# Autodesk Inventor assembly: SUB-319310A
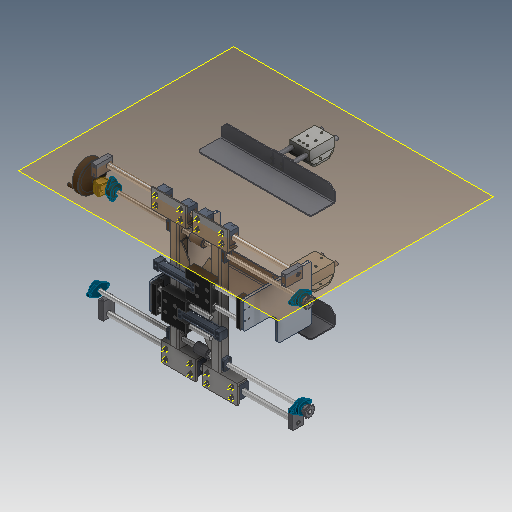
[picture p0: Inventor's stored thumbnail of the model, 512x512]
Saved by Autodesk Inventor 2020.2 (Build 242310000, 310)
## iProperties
Created: 2000-01
Part Number: SUB-319310A
Document SubType Name: Assembly
Designer: cmcgourin
Mass: 58892.8 g
Surface Area: 31424.7 cm^2
Volume: 13610.9 cm^3
Density: 4.32689 g/cm^3
Control State: 0
Master: False
Checked Out: False
Shininess: 0.0
Length Units: 11269
Angle Units: 11279
Time Units: 11290
Mass Units: 11283
Length Display Precision: 3
Angle Display Precision: 2
Compacted: True
Dimensions: 801,9x772,9x1220,3 mm
Mass: 58,893 kg
DocNumber: SUB-319310.iam
Folder: .
VDS_Category: 3D Komponenten
Density: 0.0
Volumn: 0.0
Area: 0.0
PropertySet Name: Model Information
Author: cmcgourin
Revision Number: -
Title: SUB-319310A
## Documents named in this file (33)
- D:\07 - DEMODATEN\OTX 2019 - Dataset - UPDATE - Dez2019\Designs\07-Packing machine\SUB-319310.iam
- D:\07 - DEMODATEN\OTX 2019 - Dataset - UPDATE - Dez2019\Designs\07-Packing machine\A105229.iam
- D:\07 - DEMODATEN\OTX 2019 - Dataset - UPDATE - Dez2019\Designs\07-Packing machine\Parts\ADSK-011474.ipt
- D:\07 - DEMODATEN\OTX 2019 - Dataset - UPDATE - Dez2019\Designs\07-Packing machine\Parts\ADSK-011327.ipt
- D:\07 - DEMODATEN\OTX 2019 - Dataset - UPDATE - Dez2019\Designs\07-Packing machine\500571.iam
- D:\07 - DEMODATEN\OTX 2019 - Dataset - UPDATE - Dez2019\Designs\07-Packing machine\Parts\ADSK-011325.ipt
- D:\07 - DEMODATEN\OTX 2019 - Dataset - UPDATE - Dez2019\Designs\07-Packing machine\Parts\ADSK-011507.ipt
- D:\07 - DEMODATEN\OTX 2019 - Dataset - UPDATE - Dez2019\Designs\07-Packing machine\Parts\ADSK-011515.ipt
- D:\07 - DEMODATEN\OTX 2019 - Dataset - UPDATE - Dez2019\Designs\07-Packing machine\Parts\ADSK-011726.ipt
- D:\07 - DEMODATEN\OTX 2019 - Dataset - UPDATE - Dez2019\Designs\07-Packing machine\Parts\ADSK-011516.ipt
- D:\07 - DEMODATEN\OTX 2019 - Dataset - UPDATE - Dez2019\Designs\07-Packing machine\Parts\ADSK-011714.ipt
- D:\07 - DEMODATEN\OTX 2019 - Dataset - UPDATE - Dez2019\Designs\07-Packing machine\Parts\ADSK-011333.ipt
- D:\07 - DEMODATEN\OTX 2019 - Dataset - UPDATE - Dez2019\Designs\07-Packing machine\Parts\ADSK-011517.ipt
- D:\07 - DEMODATEN\OTX 2019 - Dataset - UPDATE - Dez2019\Designs\07-Packing machine\Parts\ADSK-011768.ipt
- D:\07 - DEMODATEN\OTX 2019 - Dataset - UPDATE - Dez2019\Designs\07-Packing machine\Parts\ADSK-011309.ipt
- D:\07 - DEMODATEN\OTX 2019 - Dataset - UPDATE - Dez2019\Designs\07-Packing machine\Parts\ADSK-011723.ipt
- D:\07 - DEMODATEN\OTX 2019 - Dataset - UPDATE - Dez2019\Designs\07-Packing machine\Parts\ADSK-011565.ipt
- D:\07 - DEMODATEN\OTX 2019 - Dataset - UPDATE - Dez2019\Designs\07-Packing machine\Parts\ADSK-011627.ipt
- D:\07 - DEMODATEN\OTX 2019 - Dataset - UPDATE - Dez2019\Designs\07-Packing machine\Parts\ADSK-011639.ipt
- D:\07 - DEMODATEN\OTX 2019 - Dataset - UPDATE - Dez2019\Designs\07-Packing machine\A102253.iam
- D:\07 - DEMODATEN\OTX 2019 - Dataset - UPDATE - Dez2019\Content Center Files\de-DE\ISO 4762(2)\ISO 4762 - M8 x 16ISO.ipt
- D:\07 - DEMODATEN\OTX 2019 - Dataset - UPDATE - Dez2019\Content Center Files\de-DE\ISO 4762(2)\ISO 4762 - M8 x 60ISO.ipt
- D:\07 - DEMODATEN\OTX 2019 - Dataset - UPDATE - Dez2019\Content Center Files\de-DE\ISO 4762(2)\ISO 4762 - M8 x 45ISO.ipt
- D:\07 - DEMODATEN\OTX 2019 - Dataset - UPDATE - Dez2019\Content Center Files\de-DE\ISO 4762(2)\ISO 4762 - M6 x 30ISO.ipt
- D:\07 - DEMODATEN\OTX 2019 - Dataset - UPDATE - Dez2019\Content Center Files\de-DE\ISO 4762(2)\ISO 4762 - M12 x 25ISO.ipt
- D:\07 - DEMODATEN\OTX 2019 - Dataset - UPDATE - Dez2019\Content Center Files\de-DE\DIN 125-1  B\DIN 125-1 - B 8,4.ipt
- D:\07 - DEMODATEN\OTX 2019 - Dataset - UPDATE - Dez2019\Content Center Files\de-DE\ISO 4032(1)\ISO 4032 - M8DIN EN.ipt
- D:\07 - DEMODATEN\OTX 2019 - Dataset - UPDATE - Dez2019\Content Center Files\de-DE\ISO 2491 - A\ISO 2491 - A  5 x 3 x 22.ipt
- D:\07 - DEMODATEN\OTX 2019 - Dataset - UPDATE - Dez2019\Content Center Files\de-DE\ISO 4028\ISO 4028 - M5 x 10 - ISO.ipt
- D:\07 - DEMODATEN\OTX 2019 - Dataset - UPDATE - Dez2019\Content Center Files\de-DE\ISO 2491 - A\ISO 2491 - A  5 x 3 x 56.ipt
- D:\07 - DEMODATEN\OTX 2019 - Dataset - UPDATE - Dez2019\Content Center Files\de-DE\DIN 125-1  B\DIN 125-1 - B 6,4.ipt
- D:\07 - DEMODATEN\OTX 2019 - Dataset - UPDATE - Dez2019\Content Center Files\de-DE\ISO 4762(2)\ISO 4762 - M6 x 20ISO.ipt
- D:\07 - DEMODATEN\OTX 2019 - Dataset - UPDATE - Dez2019\Content Center Files\de-DE\ISO 4762(2)\ISO 4762 - M6 x 50ISO.ipt
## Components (150 placed, 32 different names)
1. 500571:1 [sub-assembly] — Fluchtend:16, Fluchtend:18, Passend:79, Passend:86, Passend:87, Passend:88, Passend:89, Passend:90, Passend:91, Passend:108, Passend:111, Passend:122, Passend:123, Passend:133, Passend:136, Passend:137, Passend:183, Passend:184, Passend:185, Passend:186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
2. 500571:2 [sub-assembly] — Fluchtend:17, Passend:78, Fluchtend:19, Passend:80, Passend:81, Passend:82, Passend:83, Passend:84, Passend:85, Passend:112, Passend:113, Passend:120, Passend:121, Passend:132, Passend:134, Passend:135, Passend:176, Passend:179, Passend:180, Passend:181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
3. ADSK-011474:1 — Fluchtend:238, Mate:71, Passend:267, Passend:269, Passend:271, Passend:273, Fluchtend:239, Fluchtend:244, Fluchtend:246
4. ADSK-011327:1 — Einfügen:71, Passend:263, Einfügen:82
5. ADSK-011327:2 — Einfügen:49, Fluchtend:23
6. ADSK-011327:3 — Einfügen:50, Fluchtend:23, Winkel:13
7. ADSK-011507:2 — Passend:244, Passend:262, Einfügen:71, Einfügen:72
8. ADSK-011325:6 — Passend:108, Passend:187, Passend:188, Passend:244
9. ADSK-011714:3 — Passend:175, Fluchtend:24, Passend:178, Einfügen:69
10. ADSK-011515:1 — Passend:300, Fluchtend:309, Passend:302, Passend:304, Passend:307, Fluchtend:308
11. ADSK-011516:1 — Fluchtend:26, Passend:228, Passend:237, Passend:238, Fluchtend:307, Passend:301, Fluchtend:309, Passend:302, Passend:303, Passend:308, Passend:309, Passend:310
12. ADSK-011726:1 — Passend:303, Passend:304, Passend:307
13. ADSK-011333:1 — Passend:80, Passend:84, Passend:85, Passend:101, Passend:103, Passend:105, Passend:107
14. ADSK-011714:4 — Passend:177, Winkel:14, Fluchtend:24, Fluchtend:25, Passend:255, Fluchtend:308
15. ADSK-011516:2 — Passend:245, Fluchtend:235, Passend:246, Passend:247, Passend:249, Passend:254, Passend:261
16. ADSK-011726:2 — Passend:252, Passend:253, Passend:257
17. ADSK-011517:1 — Mate:44, Mate:48, Mate:50, Flush:7, Passend:254, Passend:257, Passend:258, Passend:259, Passend:260, Passend:261, Passend:311
18. ADSK-011714:5 — Passend:242, Winkel:15, Passend:243, Einfügen:70, Passend:256
19. ADSK-011714:6 — Mate:44, Mate:62, Flush:7, Passend:255, Passend:256
20. ADSK-011333:2 — Passend:81, Passend:82, Passend:83
21. ADSK-011768:1 — Mate:48, Mate:49, Mate:62
22. ADSK-011309:1 — Mate:49, Mate:50, Passend:311
23. ADSK-011723:1 — Einfügen:69, Fluchtend:26, Passend:228, Passend:232, Drehung:1
24. ADSK-011723:2 — Einfügen:70, Passend:245, Fluchtend:235, Passend:246, Passend:248, Passend:250, Drehung:1
25. ADSK-011565:1 — Passend:170, Fluchtend:20, Passend:171
26. ADSK-011627:1 — Mate:70, Flush:9, Flush:10, Passend:264, Passend:265, Fluchtend:237
27. ADSK-011639:1 — Passend:174, Fluchtend:22, Einfügen:49, Einfügen:50
28. A102253:1 [sub-assembly] — Fluchtend:238, Mate:70, Flush:9, Flush:10, Mate:71, Fluchtend:239, Fluchtend:245
29. A105229:1 [sub-assembly] — Passend:133, Passend:136, Passend:137, Passend:170, Fluchtend:20, Passend:171
30. A105229:2 [sub-assembly] — Passend:132, Passend:134, Passend:135, Passend:172, Fluchtend:21, Passend:173
31. ADSK-011333:3 — Passend:86, Passend:90, Passend:91
32. ADSK-011333:4 — Passend:87, Passend:88, Passend:89, Passend:93, Passend:95, Passend:97, Passend:99
33. ADSK-011325:7 — Passend:111, Passend:189, Passend:190
34. ADSK-011325:8 — Passend:112, Passend:191, Passend:192
35. ADSK-011325:9 — Passend:113, Passend:193, Passend:194
36. ADSK-011325:10 — Passend:120, Passend:179, Passend:180
37. ADSK-011325:11 — Passend:121, Passend:181, Passend:182
38. ADSK-011325:12 — Passend:122, Passend:174, Passend:183, Passend:184
39. ADSK-011325:13 — Passend:123, Passend:185, Passend:186
40. ADSK-011565:4 — Passend:172, Fluchtend:21, Passend:173
41. ADSK-011327:4 — Einfügen:72, Passend:263, Winkel:16, Einfügen:81
42. ADSK-011474:2 — Fluchtend:244, Fluchtend:246
43. ADSK-011627:2
44. A102253:2 [sub-assembly] — Fluchtend:245
45. ISO 4762 M12 x 25:3 — Einfügen:81
46. ISO 4762 M12 x 25:4 — Einfügen:82
47. DIN 125-1 B B 6,4:5
48. DIN 125-1 B B 6,4:6
49. DIN 125-1 B B 6,4:7
50. DIN 125-1 B B 6,4:8
51. ISO 4762 M6 x 20:5
52. ISO 4762 M6 x 20:6
53. ISO 4762 M6 x 20:7
54. ISO 4762 M6 x 20:8
55. ISO 4762 M6 x 50:5
56. ISO 4762 M6 x 50:6
57. ISO 4762 M6 x 50:7
58. ISO 4762 M6 x 50:8
59. DIN 125-1 B B 6,4:1 — Passend:267, Passend:275, Passend:277, Passend:279, Passend:281
60. DIN 125-1 B B 6,4:2 — Passend:269
61. DIN 125-1 B B 6,4:3 — Passend:271
62. DIN 125-1 B B 6,4:4 — Passend:273
63. ISO 4762 M6 x 20:1 — Passend:275
64. ISO 4762 M6 x 20:2 — Passend:277
65. ISO 4762 M6 x 20:3 — Passend:279
66. ISO 4762 M6 x 20:4 — Passend:281
67. ISO 4762 M6 x 50:1
68. ISO 4762 M6 x 50:2
69. ISO 4762 M6 x 50:3
70. ISO 4762 M6 x 50:4
71. ISO 2491 A A  5 x 3 x 22:2 — Passend:247, Passend:248, Passend:249, Passend:251
72. ISO 4028 M5 x 10:2 — Passend:250, Passend:251
73. ISO 2491 A A  5 x 3 x 56:2 — Passend:258, Passend:259, Passend:260
74. ISO 2491 A A  5 x 3 x 22:1 — Passend:233, Passend:308, Passend:309, Passend:310
75. ISO 4028 M5 x 10:1 — Passend:232, Passend:233
76. ISO 2491 A A  5 x 3 x 56:1 — Passend:237, Passend:238, Fluchtend:307
77. ISO 4762 M6 x 30:1
78. ISO 4762 M6 x 30:2
79. ISO 4762 M6 x 30:3
80. ISO 4762 M6 x 30:4
81. ISO 4762 M6 x 30:5
82. ISO 4762 M6 x 30:6
83. ISO 4762 M6 x 30:7
84. ISO 4762 M6 x 30:8
85. ISO 4762 M12 x 25:1
86. ISO 4762 M12 x 25:2
87. DIN 125-1 B B 8,4:1 — Passend:196
88. DIN 125-1 B B 8,4:2 — Passend:198
89. DIN 125-1 B B 8,4:3 — Passend:200
90. DIN 125-1 B B 8,4:4 — Passend:202
91. DIN 125-1 B B 8,4:5 — Passend:204
92. DIN 125-1 B B 8,4:6 — Passend:206
93. DIN 125-1 B B 8,4:7 — Passend:208
94. DIN 125-1 B B 8,4:8 — Passend:210
95. DIN 125-1 B B 8,4:9 — Passend:212
96. DIN 125-1 B B 8,4:10 — Passend:214
97. DIN 125-1 B B 8,4:11 — Passend:216
98. DIN 125-1 B B 8,4:12 — Passend:218
99. DIN 125-1 B B 8,4:13 — Passend:220
100. DIN 125-1 B B 8,4:14 — Passend:222
101. DIN 125-1 B B 8,4:15 — Passend:224
102. DIN 125-1 B B 8,4:16 — Passend:226
103. DIN EN 24032 M8:1
104. DIN EN 24032 M8:2
105. DIN EN 24032 M8:3
106. DIN EN 24032 M8:4
107. DIN EN 24032 M8:5
108. DIN EN 24032 M8:6
109. DIN EN 24032 M8:7
110. DIN EN 24032 M8:8
111. DIN EN 24032 M8:9
112. DIN EN 24032 M8:10
113. DIN EN 24032 M8:11
114. DIN EN 24032 M8:12
115. DIN EN 24032 M8:13
116. DIN EN 24032 M8:14
117. DIN EN 24032 M8:15
118. DIN EN 24032 M8:16
119. ISO 4762 M8 x 45:1
120. ISO 4762 M8 x 45:2
121. ISO 4762 M8 x 45:3
122. ISO 4762 M8 x 45:4
123. ISO 4762 M8 x 45:5
124. ISO 4762 M8 x 45:6
125. ISO 4762 M8 x 45:7
126. ISO 4762 M8 x 45:8
127. ISO 4762 M8 x 60:1
128. ISO 4762 M8 x 60:2
129. ISO 4762 M8 x 60:3
130. ISO 4762 M8 x 60:4
131. ISO 4762 M8 x 60:5
132. ISO 4762 M8 x 60:6
133. ISO 4762 M8 x 60:7
134. ISO 4762 M8 x 60:8
135. ISO 4762 M8 x 60:9
136. ISO 4762 M8 x 60:10
137. ISO 4762 M8 x 60:11
138. ISO 4762 M8 x 60:12
139. ISO 4762 M8 x 60:13
140. ISO 4762 M8 x 60:14
141. ISO 4762 M8 x 60:15
142. ISO 4762 M8 x 60:16
143. ISO 4762 M8 x 16:1 — Passend:93
144. ISO 4762 M8 x 16:2 — Passend:95
145. ISO 4762 M8 x 16:3 — Passend:97
146. ISO 4762 M8 x 16:4 — Passend:99
147. ISO 4762 M8 x 16:5 — Passend:101
148. ISO 4762 M8 x 16:6 — Passend:103
149. ISO 4762 M8 x 16:7 — Passend:105
150. ISO 4762 M8 x 16:8 — Passend:107
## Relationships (169: Mate 132, Flush 24, Insert 8, Angle 4, RelateRotation 1)
- Mate:44: ADSK-011517:1 ↔ ADSK-011714:6
- Mate:48: ADSK-011517:1 ↔ ADSK-011768:1
- Mate:49: ADSK-011768:1 ↔ ADSK-011309:1
- Mate:50: ADSK-011517:1 ↔ ADSK-011309:1
- Mate:62: ADSK-011714:6 ↔ ADSK-011768:1
- Flush:7: ADSK-011517:1 ↔ ADSK-011714:6
- Fluchtend:238 [Flush]: ADSK-011474:1 ↔ A102253:1
- Mate:70: ADSK-011627:1 ↔ A102253:1
- Flush:9: ADSK-011627:1 ↔ A102253:1
- Flush:10: ADSK-011627:1 ↔ A102253:1
- Mate:71: ADSK-011474:1 ↔ A102253:1
- Fluchtend:16 [Flush]: 500571:1
- Fluchtend:17 [Flush]: 500571:2
- Fluchtend:18 [Flush]: 500571:1
- Passend:78 [Mate]: 500571:2
- Passend:79 [Mate]: 500571:1
- Fluchtend:19 [Flush]: 500571:2
- Passend:80 [Mate]: 500571:2 ↔ ADSK-011333:1
- Passend:81 [Mate]: 500571:2 ↔ ADSK-011333:2
- Passend:82 [Mate]: 500571:2 ↔ ADSK-011333:2
- Passend:83 [Mate]: 500571:2 ↔ ADSK-011333:2
- Passend:84 [Mate]: 500571:2 ↔ ADSK-011333:1
- Passend:85 [Mate]: 500571:2 ↔ ADSK-011333:1
- Passend:86 [Mate]: 500571:1 ↔ ADSK-011333:3
- Passend:87 [Mate]: 500571:1 ↔ ADSK-011333:4
- Passend:88 [Mate]: 500571:1 ↔ ADSK-011333:4
- Passend:89 [Mate]: 500571:1 ↔ ADSK-011333:4
- Passend:90 [Mate]: 500571:1 ↔ ADSK-011333:3
- Passend:91 [Mate]: 500571:1 ↔ ADSK-011333:3
- Passend:93 [Mate]: ADSK-011333:4 ↔ ISO 4762 M8 x 16:1
- Passend:95 [Mate]: ADSK-011333:4 ↔ ISO 4762 M8 x 16:2
- Passend:97 [Mate]: ADSK-011333:4 ↔ ISO 4762 M8 x 16:3
- Passend:99 [Mate]: ADSK-011333:4 ↔ ISO 4762 M8 x 16:4
- Passend:101 [Mate]: ADSK-011333:1 ↔ ISO 4762 M8 x 16:5
- Passend:103 [Mate]: ADSK-011333:1 ↔ ISO 4762 M8 x 16:6
- Passend:105 [Mate]: ADSK-011333:1 ↔ ISO 4762 M8 x 16:7
- Passend:107 [Mate]: ADSK-011333:1 ↔ ISO 4762 M8 x 16:8
- Passend:108 [Mate]: 500571:1 ↔ ADSK-011325:6
- Passend:111 [Mate]: 500571:1 ↔ ADSK-011325:7
- Passend:112 [Mate]: 500571:2 ↔ ADSK-011325:8
- Passend:113 [Mate]: 500571:2 ↔ ADSK-011325:9
- Passend:120 [Mate]: 500571:2 ↔ ADSK-011325:10
- Passend:121 [Mate]: 500571:2 ↔ ADSK-011325:11
- Passend:122 [Mate]: 500571:1 ↔ ADSK-011325:12
- Passend:123 [Mate]: 500571:1 ↔ ADSK-011325:13
- Passend:132 [Mate]: 500571:2 ↔ A105229:2
- Passend:133 [Mate]: 500571:1 ↔ A105229:1
- Passend:134 [Mate]: 500571:2 ↔ A105229:2
- Passend:135 [Mate]: 500571:2 ↔ A105229:2
- Passend:136 [Mate]: 500571:1 ↔ A105229:1
- Passend:137 [Mate]: 500571:1 ↔ A105229:1
- Passend:170 [Mate]: ADSK-011565:1 ↔ A105229:1
- Fluchtend:20 [Flush]: ADSK-011565:1 ↔ A105229:1
- Passend:171 [Mate]: ADSK-011565:1 ↔ A105229:1
- Passend:172 [Mate]: A105229:2 ↔ ADSK-011565:4
- Fluchtend:21 [Flush]: A105229:2 ↔ ADSK-011565:4
- Passend:173 [Mate]: A105229:2 ↔ ADSK-011565:4
- Passend:174 [Mate]: ADSK-011639:1 ↔ ADSK-011325:12
- Fluchtend:22 [Flush]: ADSK-011639:1
- Einfügen:49 [Insert]: ADSK-011327:2 ↔ ADSK-011639:1
- Einfügen:50 [Insert]: ADSK-011327:3 ↔ ADSK-011639:1
- Fluchtend:23 [Flush]: ADSK-011327:2 ↔ ADSK-011327:3
- Winkel:13 [Angle]: ADSK-011327:3
- Passend:175 [Mate]: ADSK-011714:3
- Passend:176 [Mate]: 500571:2
- Passend:177 [Mate]: ADSK-011714:4
- Winkel:14 [Angle]: ADSK-011714:4
- Fluchtend:24 [Flush]: ADSK-011714:3 ↔ ADSK-011714:4
- Passend:178 [Mate]: ADSK-011714:3
- Fluchtend:25 [Flush]: ADSK-011714:4
- Passend:179 [Mate]: 500571:2 ↔ ADSK-011325:10
- Passend:180 [Mate]: 500571:2 ↔ ADSK-011325:10
- Passend:181 [Mate]: 500571:2 ↔ ADSK-011325:11
- Passend:182 [Mate]: 500571:2 ↔ ADSK-011325:11
- Passend:183 [Mate]: 500571:1 ↔ ADSK-011325:12
- Passend:184 [Mate]: 500571:1 ↔ ADSK-011325:12
- Passend:185 [Mate]: 500571:1 ↔ ADSK-011325:13
- Passend:186 [Mate]: 500571:1 ↔ ADSK-011325:13
- Passend:187 [Mate]: 500571:1 ↔ ADSK-011325:6
- Passend:188 [Mate]: 500571:1 ↔ ADSK-011325:6
- Passend:189 [Mate]: 500571:1 ↔ ADSK-011325:7
- Passend:190 [Mate]: 500571:1 ↔ ADSK-011325:7
- Passend:191 [Mate]: 500571:2 ↔ ADSK-011325:8
- Passend:192 [Mate]: 500571:2 ↔ ADSK-011325:8
- Passend:193 [Mate]: 500571:2 ↔ ADSK-011325:9
- Passend:194 [Mate]: 500571:2 ↔ ADSK-011325:9
- Passend:196 [Mate]: 500571:1 ↔ DIN 125-1 B B 8,4:1
- Passend:198 [Mate]: 500571:1 ↔ DIN 125-1 B B 8,4:2
- Passend:200 [Mate]: 500571:1 ↔ DIN 125-1 B B 8,4:3
- Passend:202 [Mate]: 500571:1 ↔ DIN 125-1 B B 8,4:4
- Passend:204 [Mate]: 500571:2 ↔ DIN 125-1 B B 8,4:5
- Passend:206 [Mate]: 500571:2 ↔ DIN 125-1 B B 8,4:6
- Passend:208 [Mate]: 500571:2 ↔ DIN 125-1 B B 8,4:7
- Passend:210 [Mate]: 500571:2 ↔ DIN 125-1 B B 8,4:8
- Passend:212 [Mate]: 500571:1 ↔ DIN 125-1 B B 8,4:9
- Passend:214 [Mate]: 500571:1 ↔ DIN 125-1 B B 8,4:10
- Passend:216 [Mate]: 500571:1 ↔ DIN 125-1 B B 8,4:11
- Passend:218 [Mate]: 500571:1 ↔ DIN 125-1 B B 8,4:12
- Passend:220 [Mate]: 500571:2 ↔ DIN 125-1 B B 8,4:13
- Passend:222 [Mate]: 500571:2 ↔ DIN 125-1 B B 8,4:14
- Passend:224 [Mate]: 500571:2 ↔ DIN 125-1 B B 8,4:15
- Passend:226 [Mate]: 500571:2 ↔ DIN 125-1 B B 8,4:16
- Einfügen:69 [Insert]: ADSK-011714:3 ↔ ADSK-011723:1
- Fluchtend:26 [Flush]: ADSK-011516:1 ↔ ADSK-011723:1
- Passend:228 [Mate]: ADSK-011516:1 ↔ ADSK-011723:1
- Passend:232 [Mate]: ADSK-011723:1 ↔ ISO 4028 M5 x 10:1
- Passend:233 [Mate]: ISO 2491 A A  5 x 3 x 22:1 ↔ ISO 4028 M5 x 10:1
- Passend:237 [Mate]: ADSK-011516:1 ↔ ISO 2491 A A  5 x 3 x 56:1
- Passend:238 [Mate]: ADSK-011516:1 ↔ ISO 2491 A A  5 x 3 x 56:1
- Fluchtend:307 [Flush]: ADSK-011516:1 ↔ ISO 2491 A A  5 x 3 x 56:1
- Passend:241 [Mate]: 500571:1
- Passend:242 [Mate]: ADSK-011714:5
- Winkel:15 [Angle]: ADSK-011714:5
- Passend:243 [Mate]: ADSK-011714:5
- Einfügen:70 [Insert]: ADSK-011714:5 ↔ ADSK-011723:2
- Passend:244 [Mate]: ADSK-011507:2 ↔ ADSK-011325:6
- Passend:245 [Mate]: ADSK-011516:2 ↔ ADSK-011723:2
- Fluchtend:235 [Flush]: ADSK-011516:2 ↔ ADSK-011723:2
- Passend:246 [Mate]: ADSK-011516:2 ↔ ADSK-011723:2
- Passend:247 [Mate]: ADSK-011516:2 ↔ ISO 2491 A A  5 x 3 x 22:2
- Passend:248 [Mate]: ADSK-011723:2 ↔ ISO 2491 A A  5 x 3 x 22:2
- Passend:249 [Mate]: ADSK-011516:2 ↔ ISO 2491 A A  5 x 3 x 22:2
- Passend:250 [Mate]: ADSK-011723:2 ↔ ISO 4028 M5 x 10:2
- Passend:251 [Mate]: ISO 2491 A A  5 x 3 x 22:2 ↔ ISO 4028 M5 x 10:2
- Passend:252 [Mate]: ADSK-011726:2
- Passend:253 [Mate]: ADSK-011726:2
- Passend:254 [Mate]: ADSK-011516:2 ↔ ADSK-011517:1
- Passend:255 [Mate]: ADSK-011714:4 ↔ ADSK-011714:6
- Passend:256 [Mate]: ADSK-011714:5 ↔ ADSK-011714:6
- Passend:257 [Mate]: ADSK-011726:2 ↔ ADSK-011517:1
- Passend:258 [Mate]: ADSK-011517:1 ↔ ISO 2491 A A  5 x 3 x 56:2
- Passend:259 [Mate]: ADSK-011517:1 ↔ ISO 2491 A A  5 x 3 x 56:2
- Passend:260 [Mate]: ADSK-011517:1 ↔ ISO 2491 A A  5 x 3 x 56:2
- Passend:261 [Mate]: ADSK-011516:2 ↔ ADSK-011517:1
- Passend:262 [Mate]: ADSK-011507:2
- Einfügen:71 [Insert]: ADSK-011327:1 ↔ ADSK-011507:2
- Einfügen:72 [Insert]: ADSK-011507:2 ↔ ADSK-011327:4
- Passend:263 [Mate]: ADSK-011327:1 ↔ ADSK-011327:4
- Winkel:16 [Angle]: ADSK-011327:4
- Passend:264 [Mate]: ADSK-011627:1
- Passend:265 [Mate]: ADSK-011627:1
- Fluchtend:237 [Flush]: ADSK-011627:1
- Passend:267 [Mate]: ADSK-011474:1 ↔ DIN 125-1 B B 6,4:1
- Passend:269 [Mate]: ADSK-011474:1 ↔ DIN 125-1 B B 6,4:2
- Passend:271 [Mate]: ADSK-011474:1 ↔ DIN 125-1 B B 6,4:3
- Passend:273 [Mate]: ADSK-011474:1 ↔ DIN 125-1 B B 6,4:4
- Passend:275 [Mate]: DIN 125-1 B B 6,4:1 ↔ ISO 4762 M6 x 20:1
- Passend:277 [Mate]: DIN 125-1 B B 6,4:1 ↔ ISO 4762 M6 x 20:2
- Passend:279 [Mate]: DIN 125-1 B B 6,4:1 ↔ ISO 4762 M6 x 20:3
- Passend:281 [Mate]: DIN 125-1 B B 6,4:1 ↔ ISO 4762 M6 x 20:4
- Fluchtend:239 [Flush]: ADSK-011474:1 ↔ A102253:1
- Fluchtend:244 [Flush]: ADSK-011474:1 ↔ ADSK-011474:2
- Fluchtend:245 [Flush]: A102253:1 ↔ A102253:2
- Fluchtend:246 [Flush]: ADSK-011474:1 ↔ ADSK-011474:2
- Passend:300 [Mate]: ADSK-011515:1
- Passend:301 [Mate]: ADSK-011516:1
- Fluchtend:309 [Flush]: ADSK-011515:1 ↔ ADSK-011516:1
- Passend:302 [Mate]: ADSK-011515:1 ↔ ADSK-011516:1
- Passend:303 [Mate]: ADSK-011516:1 ↔ ADSK-011726:1
- Passend:304 [Mate]: ADSK-011515:1 ↔ ADSK-011726:1
- Passend:307 [Mate]: ADSK-011515:1 ↔ ADSK-011726:1
- Fluchtend:308 [Flush]: ADSK-011515:1 ↔ ADSK-011714:4
- Passend:308 [Mate]: ADSK-011516:1 ↔ ISO 2491 A A  5 x 3 x 22:1
- Passend:309 [Mate]: ADSK-011516:1 ↔ ISO 2491 A A  5 x 3 x 22:1
- Passend:310 [Mate]: ADSK-011516:1 ↔ ISO 2491 A A  5 x 3 x 22:1
- Einfügen:81 [Insert]: ADSK-011327:4 ↔ ISO 4762 M12 x 25:3
- Einfügen:82 [Insert]: ADSK-011327:1 ↔ ISO 4762 M12 x 25:4
- Passend:311 [Mate]: ADSK-011517:1 ↔ ADSK-011309:1
- Drehung:1 [RelateRotation]: ADSK-011723:1 ↔ ADSK-011723:2
## Named parameters: d727_d706 = 0, d728_d707 = 0, d729_d708 = 0, d730_d709 = 0, d731_d710 = 0, d732_d711 = 0, d733_d712 = 0, d734_d713 = 0, d735_d714 = 0, d736_d715 = 0, d737_d716 = 0, d738_d717 = 0, d739_d718 = 0, d740_d719 = 0, d741_d720 = 0, d742_d721 = 0, d743_d722 = 0, d744_d723 = 0, d745_d724 = 0, d746_d725 = 0, d748_d404 = 0, d749_d405 = 0, d750_d406 = 0, d751_d407 = -26.1874 mm, d752_d408 = 0
